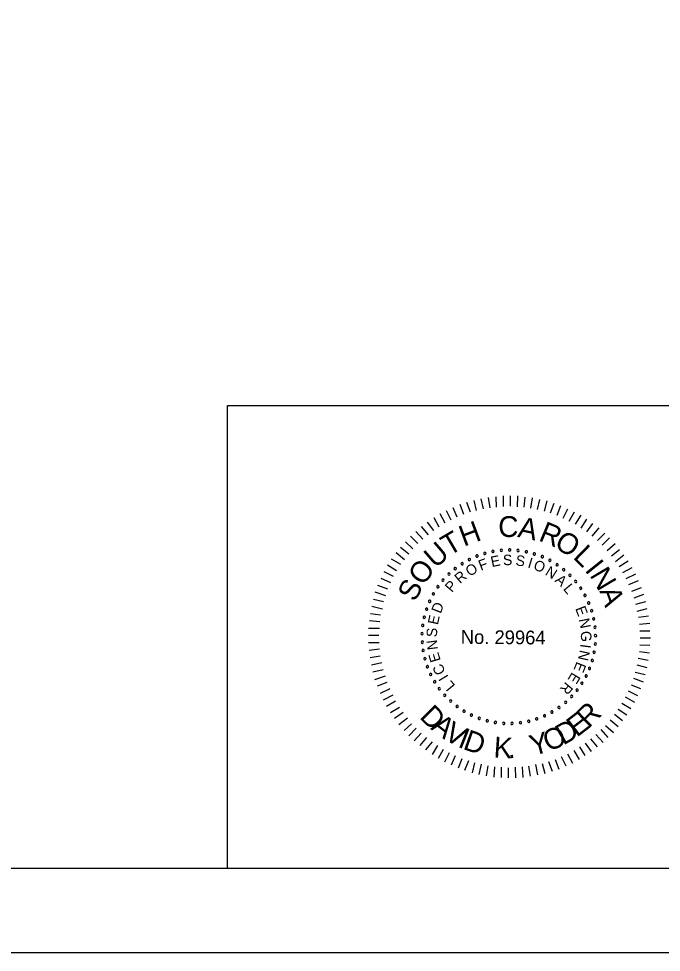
# Model space of a CAD drawing. Extents: x -121.2 to -24.9, y 6.4 to 65.6.
# Drawn here: x -64.11 to -53.92, y 6.35 to 21.15 of the extents above; entities that cross this region are included whole.
import ezdxf

# ---------------------------------------------------------------- set-up
doc = ezdxf.new("R2010")
doc.units = 0
for name, color, linetype in [('BR_BORDER LINES', 7, 'Continuous'), ('BR_TEXT', 7, 'Continuous'), ('Level 31', 7, 'Continuous')]:
    doc.layers.add(name, color=color, linetype=linetype)

msp = doc.modelspace()

# ---------------------------------------------------------------- linework, layer by layer
at = {"layer": 'BR_BORDER LINES'}
for p, q in [((-60.804, 15.017), (-46.496, 15.017)), ((-60.804, 7.683), (-60.804, 15.017)), ((-116.272, 7.683), (-26.496, 7.683))]:
    msp.add_line(p, q, dxfattribs=at)
at = {"layer": 'BR_TEXT'}
for p, q in [((-56.951, 13.326), (-57.009, 13.479)), ((-56.854, 13.352), (-56.89, 13.515)), ((-56.744, 13.379), (-56.782, 13.537)), ((-56.639, 13.398), (-56.663, 13.561)), ((-56.534, 13.409), (-56.544, 13.572)), ((-56.428, 13.415), (-56.427, 13.587)), ((-56.316, 13.421), (-56.315, 13.586)), ((-56.204, 13.413), (-56.198, 13.585)), ((-56.097, 13.405), (-56.084, 13.568)), ((-55.994, 13.393), (-55.965, 13.555)), ((-55.886, 13.372), (-55.848, 13.529)), ((-55.777, 13.343), (-55.734, 13.505)), ((-57.258, 13.202), (-57.328, 13.351)), ((-57.16, 13.247), (-57.223, 13.396)), ((-57.056, 13.292), (-57.112, 13.448)), ((-55.679, 13.315), (-55.62, 13.468)), ((-55.574, 13.28), (-55.515, 13.435)), ((-55.478, 13.233), (-55.403, 13.381)), ((-55.382, 13.187), (-55.298, 13.335)), ((-57.445, 13.092), (-57.526, 13.236)), ((-57.35, 13.155), (-57.432, 13.3)), ((-55.282, 13.138), (-55.196, 13.281)), ((-55.193, 13.073), (-55.103, 13.216)), ((-57.617, 12.967), (-57.724, 13.101)), ((-57.528, 13.035), (-57.632, 13.171)), ((-55.104, 13.015), (-55.007, 13.149)), ((-55.018, 12.946), (-54.909, 13.078)), ((-57.783, 12.829), (-57.901, 12.947)), ((-57.705, 12.902), (-57.816, 13.021)), ((-54.934, 12.879), (-54.818, 12.997)), ((-54.859, 12.805), (-54.743, 12.921)), ((-57.929, 12.663), (-58.061, 12.767)), ((-57.862, 12.747), (-57.978, 12.86)), ((-54.784, 12.722), (-54.657, 12.833)), ((-54.712, 12.636), (-54.587, 12.738)), ((-58.056, 12.497), (-58.2, 12.585)), ((-57.998, 12.574), (-58.13, 12.681)), ((-54.648, 12.547), (-54.517, 12.651)), ((-58.121, 12.399), (-58.264, 12.485)), ((-54.589, 12.468), (-54.449, 12.554)), ((-54.531, 12.37), (-54.388, 12.453)), ((-58.168, 12.308), (-58.318, 12.382)), ((-54.483, 12.278), (-54.329, 12.35)), ((-58.261, 12.107), (-58.416, 12.166)), ((-58.214, 12.21), (-58.367, 12.278)), ((-54.436, 12.179), (-54.284, 12.244)), ((-58.294, 12), (-58.458, 12.061)), ((-54.391, 12.075), (-54.24, 12.131)), ((-54.355, 11.968), (-54.202, 12.026)), ((-58.326, 11.904), (-58.489, 11.945)), ((-54.329, 11.871), (-54.168, 11.909)), ((-58.374, 11.696), (-58.536, 11.718)), ((-58.346, 11.792), (-58.512, 11.835)), ((-54.307, 11.759), (-54.146, 11.799)), ((-58.386, 11.587), (-58.551, 11.606)), ((-54.285, 11.663), (-54.127, 11.682)), ((-54.267, 11.553), (-54.105, 11.57)), ((-58.394, 11.481), (-58.566, 11.483)), ((-54.264, 11.447), (-54.103, 11.446)), ((-58.396, 11.257), (-58.568, 11.254)), ((-58.4, 11.372), (-58.567, 11.373)), ((-54.258, 11.338), (-54.095, 11.336)), ((-58.39, 11.154), (-58.555, 11.135)), ((-54.271, 11.12), (-54.109, 11.098)), ((-54.265, 11.223), (-54.105, 11.217)), ((-58.379, 11.044), (-58.542, 11.02)), ((-54.29, 11.011), (-54.132, 10.984)), ((-58.353, 10.939), (-58.52, 10.904)), ((-58.335, 10.826), (-58.498, 10.789)), ((-54.314, 10.905), (-54.154, 10.867)), ((-58.304, 10.728), (-58.469, 10.672)), ((-54.366, 10.695), (-54.213, 10.637)), ((-54.338, 10.793), (-54.178, 10.753)), ((-58.273, 10.625), (-58.429, 10.569)), ((-58.228, 10.526), (-58.382, 10.454)), ((-54.403, 10.593), (-54.253, 10.534)), ((-58.183, 10.429), (-58.335, 10.35)), ((-54.499, 10.399), (-54.346, 10.318)), ((-54.45, 10.495), (-54.3, 10.42)), ((-58.138, 10.331), (-58.283, 10.247)), ((-58.075, 10.232), (-58.22, 10.148)), ((-54.548, 10.301), (-54.407, 10.215)), ((-58.018, 10.153), (-58.152, 10.056)), ((-54.668, 10.126), (-54.539, 10.026)), ((-54.608, 10.203), (-54.469, 10.117)), ((-57.95, 10.064), (-58.084, 9.959)), ((-57.885, 9.974), (-58.002, 9.865)), ((-54.807, 9.948), (-54.682, 9.837)), ((-54.733, 10.037), (-54.61, 9.931)), ((-57.808, 9.904), (-57.927, 9.784)), ((-57.73, 9.824), (-57.844, 9.701)), ((-54.959, 9.801), (-54.846, 9.676)), ((-54.883, 9.88), (-54.77, 9.758)), ((-57.644, 9.754), (-57.753, 9.629)), ((-57.555, 9.685), (-57.662, 9.558)), ((-57.473, 9.627), (-57.557, 9.488)), ((-55.132, 9.665), (-55.037, 9.536)), ((-55.044, 9.733), (-54.938, 9.606)), ((-57.38, 9.567), (-57.464, 9.423)), ((-57.289, 9.513), (-57.361, 9.365)), ((-55.413, 9.498), (-55.331, 9.348)), ((-55.311, 9.55), (-55.228, 9.405)), ((-55.222, 9.608), (-55.134, 9.468)), ((-57.191, 9.467), (-57.256, 9.319)), ((-57.088, 9.42), (-57.147, 9.27)), ((-56.983, 9.387), (-57.044, 9.232)), ((-56.888, 9.354), (-56.925, 9.197)), ((-56.778, 9.335), (-56.818, 9.171)), ((-55.92, 9.328), (-55.884, 9.163)), ((-55.81, 9.346), (-55.77, 9.187)), ((-55.711, 9.377), (-55.655, 9.221)), ((-55.606, 9.408), (-55.55, 9.256)), ((-55.509, 9.453), (-55.437, 9.304)), ((-56.673, 9.305), (-56.699, 9.149)), ((-56.568, 9.292), (-56.58, 9.128)), ((-56.462, 9.285), (-56.464, 9.12)), ((-56.35, 9.277), (-56.352, 9.114)), ((-56.238, 9.283), (-56.235, 9.118)), ((-56.131, 9.289), (-56.121, 9.124)), ((-56.028, 9.299), (-56.001, 9.143))]:
    msp.add_line(p, q, dxfattribs=at)
for centre, start, end in [((-56.46, 12.723), 5.0653, 185.0653), ((-56.328, 12.728), 359.5268, 179.5268), ((-56.195, 12.72), 353.9884, 173.9884), ((-56.968, 12.577), 27.2191, 207.2191), ((-56.968, 12.577), 207.2191, 27.2191), ((-56.847, 12.632), 21.6807, 201.6807), ((-56.847, 12.632), 201.6807, 21.6807), ((-56.721, 12.674), 16.1422, 196.1422), ((-56.721, 12.674), 196.1422, 16.1422), ((-56.592, 12.705), 10.6038, 190.6038), ((-56.592, 12.705), 190.6038, 10.6038), ((-56.46, 12.723), 185.0653, 5.0653), ((-56.328, 12.728), 179.5268, 359.5268), ((-56.195, 12.72), 173.9884, 353.9884), ((-56.064, 12.699), 348.4499, 168.4499), ((-56.064, 12.699), 168.4499, 348.4499), ((-55.935, 12.666), 162.9114, 342.9114), ((-55.935, 12.666), 342.9114, 162.9114), ((-55.81, 12.621), 157.373, 337.373), ((-55.81, 12.621), 337.373, 157.373), ((-55.69, 12.564), 331.8345, 151.8345), ((-57.192, 12.434), 38.2961, 218.2961), ((-57.192, 12.434), 218.2961, 38.2961), ((-57.083, 12.511), 32.7576, 212.7576), ((-57.083, 12.511), 212.7576, 32.7576), ((-55.69, 12.564), 151.8345, 331.8345), ((-55.576, 12.495), 146.2961, 326.2961), ((-55.576, 12.495), 326.2961, 146.2961), ((-55.47, 12.416), 320.7576, 140.7576), ((-57.292, 12.347), 43.8345, 223.8345), ((-57.292, 12.347), 223.8345, 43.8345), ((-55.47, 12.416), 140.7576, 320.7576), ((-55.371, 12.327), 135.2191, 315.2191), ((-55.371, 12.327), 315.2191, 135.2191), ((-57.465, 12.145), 54.9114, 234.9114), ((-57.465, 12.145), 234.9114, 54.9114), ((-57.384, 12.25), 49.373, 229.373), ((-57.384, 12.25), 229.373, 49.373), ((-55.282, 12.229), 129.6807, 309.6807), ((-55.282, 12.229), 309.6807, 129.6807), ((-55.202, 12.122), 124.1422, 304.1422), ((-55.202, 12.122), 304.1422, 124.1422), ((-57.537, 12.033), 60.4499, 240.4499), ((-57.537, 12.033), 240.4499, 60.4499), ((-55.133, 12.009), 118.6038, 298.6038), ((-55.133, 12.009), 298.6038, 118.6038), ((-57.597, 11.915), 65.9884, 245.9884), ((-57.597, 11.915), 245.9884, 65.9884), ((-55.075, 11.889), 113.0653, 293.0653), ((-55.075, 11.889), 293.0653, 113.0653), ((-57.645, 11.791), 71.5268, 251.5268), ((-57.645, 11.791), 251.5268, 71.5268), ((-55.029, 11.764), 107.5268, 287.5268), ((-55.029, 11.764), 287.5268, 107.5268), ((-57.705, 11.532), 82.6038, 262.6038), ((-57.705, 11.532), 262.6038, 82.6038), ((-57.681, 11.663), 77.0653, 257.0653), ((-57.681, 11.663), 257.0653, 77.0653), ((-54.996, 11.636), 101.9884, 281.9884), ((-54.996, 11.636), 281.9884, 101.9884), ((-57.716, 11.4), 88.1422, 268.1422), ((-57.716, 11.4), 268.1422, 88.1422), ((-54.975, 11.504), 96.4499, 276.4499), ((-54.975, 11.504), 276.4499, 96.4499), ((-57.714, 11.267), 93.6807, 273.6807), ((-57.714, 11.267), 273.6807, 93.6807), ((-54.971, 11.239), 85.373, 265.373), ((-54.967, 11.372), 90.9114, 270.9114), ((-54.971, 11.239), 265.373, 85.373), ((-54.967, 11.372), 270.9114, 90.9114), ((-57.7, 11.135), 99.2191, 279.2191), ((-57.7, 11.135), 279.2191, 99.2191), ((-54.989, 11.107), 79.8345, 259.8345), ((-54.989, 11.107), 259.8345, 79.8345), ((-57.672, 11.005), 104.7576, 284.7576), ((-57.672, 11.005), 284.7576, 104.7576), ((-55.019, 10.978), 74.2961, 254.2961), ((-55.019, 10.978), 254.2961, 74.2961), ((-57.632, 10.878), 110.2961, 290.2961), ((-57.632, 10.878), 290.2961, 110.2961), ((-55.061, 10.852), 68.7576, 248.7576), ((-55.061, 10.852), 248.7576, 68.7576), ((-57.581, 10.756), 115.8345, 295.8345), ((-57.581, 10.756), 295.8345, 115.8345), ((-57.517, 10.639), 301.373, 121.373), ((-55.115, 10.731), 63.2191, 243.2191), ((-55.115, 10.731), 243.2191, 63.2191), ((-57.517, 10.639), 121.373, 301.373), ((-57.443, 10.529), 126.9114, 306.9114), ((-57.443, 10.529), 306.9114, 126.9114), ((-55.258, 10.507), 52.1422, 232.1422), ((-55.258, 10.507), 232.1422, 52.1422), ((-55.181, 10.615), 57.6807, 237.6807), ((-55.181, 10.615), 237.6807, 57.6807), ((-57.358, 10.426), 132.4499, 312.4499), ((-57.358, 10.426), 312.4499, 132.4499), ((-55.344, 10.406), 46.6038, 226.6038), ((-55.344, 10.406), 226.6038, 46.6038), ((-57.264, 10.333), 137.9884, 317.9884), ((-57.264, 10.333), 317.9884, 137.9884), ((-57.161, 10.248), 143.5268, 323.5268), ((-57.161, 10.248), 323.5268, 143.5268), ((-55.545, 10.232), 35.5268, 215.5268), ((-55.545, 10.232), 215.5268, 35.5268), ((-55.44, 10.314), 41.0653, 221.0653), ((-55.44, 10.314), 221.0653, 41.0653), ((-57.051, 10.174), 149.0653, 329.0653), ((-57.051, 10.174), 329.0653, 149.0653), ((-56.934, 10.112), 154.6038, 334.6038), ((-56.934, 10.112), 334.6038, 154.6038), ((-56.811, 10.06), 160.1422, 340.1422), ((-56.811, 10.06), 340.1422, 160.1422), ((-55.899, 10.051), 18.9114, 198.9114), ((-55.775, 10.1), 24.4499, 204.4499), ((-55.775, 10.1), 204.4499, 24.4499), ((-55.657, 10.16), 29.9884, 209.9884), ((-55.657, 10.16), 209.9884, 29.9884), ((-56.684, 10.021), 345.6807, 165.6807), ((-56.684, 10.021), 165.6807, 345.6807), ((-56.554, 9.994), 351.2191, 171.2191), ((-56.554, 9.994), 171.2191, 351.2191), ((-56.422, 9.98), 356.7576, 176.7576), ((-56.422, 9.98), 176.7576, 356.7576), ((-56.289, 9.978), 2.2961, 182.2961), ((-56.289, 9.978), 182.2961, 2.2961), ((-56.157, 9.99), 7.8345, 187.8345), ((-56.157, 9.99), 187.8345, 7.8345), ((-56.026, 10.014), 13.373, 193.373), ((-56.026, 10.014), 193.373, 13.373), ((-55.899, 10.051), 198.9114, 18.9114)]:
    msp.add_arc(centre, 0.0187, start, end, dxfattribs=at)
at = {"layer": 'Level 31'}
msp.add_lwpolyline([(-121.161, 6.35), (-25.161, 6.35), (-25.161, 65.017), (-121.161, 65.017)], close=True, dxfattribs=at)

# ---------------------------------------------------------------- texts
at = {"layer": 'BR_TEXT'}
for s, height, rotation, p in [('H', 0.331, 20.3637, (-57.055, 12.779)), ('C', 0.331, 359.5482, (-56.51, 12.935)), ('A', 0.331, 348.1981, (-56.213, 12.937)), ('R', 0.331, 337.4344, (-55.884, 12.884)), ('T', 0.331, 30.4992, (-57.29, 12.626)), ('O', 0.33, 326.5869, (-55.638, 12.786)), ('U', 0.331, 40.8022, (-57.506, 12.426)), ('L', 0.331, 315.9488, (-55.338, 12.605)), ('F', 0.166, 20.6127, (-56.785, 12.398)), ('E', 0.166, 11.4103, (-56.611, 12.456)), ('S', 0.166, 2.208, (-56.431, 12.485)), ('S', 0.166, 352.6608, (-56.241, 12.485)), ('I', 0.166, 343.1136, (-56.053, 12.453)), ('I', 0.331, 308.6613, (-55.148, 12.407)), ('O', 0.331, 52.0267, (-57.705, 12.149)), ('O', 0.166, 30.8477, (-56.965, 12.302)), ('O', 0.166, 338.4392, (-55.964, 12.426)), ('N', 0.166, 328.2042, (-55.778, 12.342)), ('N', 0.331, 300.7037, (-55.066, 12.329)), ('R', 0.166, 40.3949, (-57.115, 12.185)), ('A', 0.166, 318.657, (-55.621, 12.235)), ('S', 0.33, 63.2511, (-57.826, 11.894)), ('P', 0.166, 49.9421, (-57.243, 12.045)), ('L', 0.166, 309.4546, (-55.488, 12.109)), ('A', 0.331, 289.4792, (-54.908, 12.081)), ('D', 0.166, 69.0364, (-57.421, 11.711)), ('E', 0.166, 291.049, (-55.291, 11.801)), ('E', 0.166, 78.2388, (-57.466, 11.533)), ('N', 0.166, 281.8466, (-55.232, 11.628)), ('S', 0.166, 87.786, (-57.481, 11.344)), ('No. 29964', 0.218, 359.5268, (-57.104, 11.241)), ('G', 0.166, 272.2995, (-55.201, 11.441)), ('N', 0.166, 97.3332, (-57.464, 11.154)), ('E', 0.166, 106.5355, (-57.419, 10.977)), ('N', 0.166, 257.7339, (-55.214, 11.151)), ('I', 0.166, 262.4084, (-55.202, 11.244)), ('C', 0.166, 116.4266, (-57.339, 10.797)), ('E', 0.166, 248.1867, (-55.262, 10.968)), ('I', 0.166, 121.1011, (-57.291, 10.717)), ('L', 0.166, 129.9595, (-57.183, 10.578)), ('E', 0.166, 238.9844, (-55.337, 10.8)), ('R', 0.166, 229.782, (-55.437, 10.647)), ('D', 0.329, 315.4053, (-57.771, 10.07)), ('R', 0.329, 44.5947, (-55.075, 9.895)), ('A', 0.329, 322.8377, (-57.593, 9.895)), ('E', 0.329, 37.5339, (-55.263, 9.751)), ('V', 0.329, 330.5179, (-57.387, 9.739)), ('O', 0.329, 22.4212, (-55.717, 9.527)), ('D', 0.329, 30.1015, (-55.479, 9.626)), ('I', 0.329, 338.1981, (-57.163, 9.613)), ('D', 0.329, 340.7995, (-57.083, 9.577)), ('K', 0.329, 356.098, (-56.589, 9.442)), ('Y', 0.329, 14.8649, (-55.962, 9.462)), ('.', 0.329, 3.1588, (-56.353, 9.426))]:
    msp.add_text(s, height=height, rotation=rotation, dxfattribs=at).set_placement(p)

doc.saveas('drawing.dxf')
